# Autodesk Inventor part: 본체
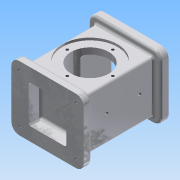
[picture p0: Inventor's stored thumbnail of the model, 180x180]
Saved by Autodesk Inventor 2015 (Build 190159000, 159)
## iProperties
Created: 2017-08
Part Number: 본체
Material: 알루미늄 6061
Document SubType Name: Modeling
Designer: Administrator
Density: 2.7 g/cm^3
Appearance: 알루미늄 - 평지
Author: Administrator
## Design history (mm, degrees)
sketch "스케치1"
  geometry: L1 (46, 41)-(-46, 41); L2 (-46, 41)-(-46, -41); L3 (-46, -41)-(46, -41); L4 (46, -41)-(46, 41); L5 (46, 41)-(-46, -41); L6 (-46, 41)-(46, -41); 1 further point
  constraints: 12 end point, 2 midpoint, 2 parallel, 1 horizontal, 1 perpendicular
  dimensions: "d0" = 92 distance of L2.end L3.end; "d1" = 82 distance of L1.end L2.end
extrude "돌출1" new body sketch "스케치1" distance "d2" = 10; taper "d3" = 0 deg
sketch "스케치2"
  geometry: L1 (-37, -33)-(37, -33); L2 (37, -33)-(37, 33); L3 (37, 33)-(-37, 33); L4 (-37, 33)-(-37, -33); L5 (-37, -33)-(37, 33); L6 (37, -33)-(-37, 33); 1 further point
  constraints: 12 end point, 2 midpoint, 2 parallel, 1 horizontal, 1 perpendicular
  dimensions: "d4" = 74 distance of L2.end L3.end; "d5" = 66 distance of L1.end L2.end
extrude "돌출2" join sketch "스케치2" distance "d6" = 88; taper "d7" = 0 deg
sketch "스케치3"
  geometry: L1 (-46, -41)-(46, -41); L2 (46, -41)-(46, 41); L3 (46, 41)-(-46, 41); L4 (-46, 41)-(-46, -41); L5 (-46, -41)-(46, 41); L6 (46, -41)-(-46, 41); 1 further point
  constraints: 12 end point, 2 midpoint, 2 parallel, 1 horizontal, 1 perpendicular
  dimensions: "d8" = 92 distance of L2.end L3.end; "d9" = 82 distance of L1.end L2.end
extrude "돌출3" join sketch "스케치3" distance "d10" = 10; taper "d11" = 0 deg
sketch "스케치4"
  geometry: L1 (-24, -24)-(24, -24); L2 (24, -24)-(24, 24); L3 (24, 24)-(-24, 24); L4 (-24, 24)-(-24, -24); L5 (-24, -24)-(24, 24); L6 (24, -24)-(-24, 24); 1 further point
  constraints: 12 end point, 2 midpoint, 2 parallel, 1 horizontal, 1 perpendicular
  dimensions: "d12" = 48 distance of L2.end L3.end; "d13" = 48 distance of L1.end L2.end
extrude "돌출4" cut sketch "스케치4" distance "d14" = 16; taper "d15" = 0 deg
sketch "스케치5"
  geometry: L1 (-26, -26)-(26, -26); L2 (26, -26)-(26, 26); L3 (26, 26)-(-26, 26); L4 (-26, 26)-(-26, -26); L5 (-26, -26)-(26, 26); L6 (26, -26)-(-26, 26); 1 further point
  constraints: 12 end point, 2 midpoint, 2 parallel, 1 horizontal, 1 perpendicular
  dimensions: "d16" = 52 distance of L2.end L3.end; "d17" = 52 distance of L1.end L2.end
extrude "돌출5" cut sketch "스케치5" distance "d18" = 8; taper "d19" = 0 deg
sketch "스케치10"
  geometry: L1 (-9, -10)-(83, -10) reference; C1 r 35 at (37, 44); 2 further points
  constraints: 1 centre point, 1 midpoint, 1 vertical alignment
  dimensions: "d26" = 54 distance from line of L1 C1.centre; "d27" = 70 diameter of C1
extrude "돌출7" cut sketch "스케치10" distance "d28" = 3; taper "d29" = 0 deg
sketch "스케치11"
  geometry: C1 r 24 at (0, 0); C2 r 35 at (0, 0) reference; 1 further point
  constraints: 1 centre point, 1 concentric
  dimensions: "d30" = 48 diameter of C1
extrude "돌출8" cut sketch "스케치11" distance "d31" = 8; taper "d32" = 0 deg
sketch "스케치12"
  geometry: C1 r 35 at (37, 44); C2 r 24 at (37, 44) reference; 1 further point
  constraints: 1 centre point, 1 concentric
  dimensions: "d33" = 70 diameter of C1
extrude "돌출9" cut sketch "스케치12" distance "d34" = 3; taper "d35" = 0 deg
sketch "스케치13"
  geometry: C1 r 24 at (0, 0); C2 r 24 at (0, 0) reference; 1 further point
  constraints: 1 centre point, 1 concentric
  dimensions: "d36" = 48 diameter of C1
extrude "돌출10" cut sketch "스케치13" distance "d37" = 8; taper "d38" = 0 deg
sketch "스케치14"
  geometry: L1 (-22, -22)-(22, -22); L2 (22, -22)-(22, 22); L3 (22, 22)-(-22, 22); L4 (-22, 22)-(-22, -22); L5 (-22, -22)-(22, 22); L6 (22, -22)-(-22, 22); 1 further point
  constraints: 12 end point, 2 midpoint, 2 parallel, 1 horizontal, 1 perpendicular
  dimensions: "d39" = 44 distance of L2.end L3.end; "d40" = 44 distance of L1.end L2.end
extrude "돌출11" cut sketch "스케치14" distance "d41" = 74; taper "d42" = 0 deg
sketch "스케치15"
  geometry: L1 (-46, -54)-(46, -54) reference; C1 r 24 at (0, 0); C2 r 24 at (0, 0) reference; 2 further points
  constraints: 1 centre point, 1 concentric, 1 midpoint, 1 vertical alignment
  dimensions: "d43" = 48 diameter of C1
extrude "돌출12" cut sketch "스케치15" stored distance "d44" = 74; taper "d45" = 0 deg
sketch "스케치16"
  geometry: L1 (-46, -54)-(46, -54) reference; 3 further points
  constraints: 1 midpoint, 1 vertical alignment
  dimensions: "d46" = 83 distance from line of point (0, 29) L1
node "작업 평면1"
sketch "스케치17"
  geometry: L1 (-46, -41)-(-46, 41) reference; L2 (-46, 41)-(46, 41) reference; 2 further points
  dimensions: "d57" = 10 distance from line of L1 point (-36, 31); "d58" = 10 distance from line of L2 point (-36, 31)
node "작업 평면2"
sketch "스케치18"
  geometry: L1 (-8, -10)-(74, -10) reference; 3 further points
  constraints: 1 midpoint, 1 vertical alignment
  dimensions: "d72" = 38 distance from line of L1 point (33, 28)
hole "구멍3" sketch "스케치18" at (33, 28) diameter "d73" = 4.459; stored, may be unused: countersink angle "d77" = 90 deg, drill point angle "d79" = 118 deg; dims "d74" = 10, "d75" = 4, "d76" = 2, "d78" = 12.8
fillet "모깎기3" dims "d85" = 3
hole "구멍4" sketch "스케치17" diameter "d86" = 3.459; stored, may be unused: countersink angle "d90" = 90 deg, drill point angle "d92" = 118 deg; dims "d87" = 4, "d88" = 4, "d89" = 2, "d91" = 6
fillet "모깎기4" dims "d99" = 10
fillet "모깎기5" dims "d100" = 10
fillet "모깎기6" dims "d101" = 3
fillet "모깎기7" dims "d102" = 3
fillet "모깎기8" dims "d103" = 3
fillet "모깎기9" dims "d104" = 3
fillet "모깎기10" dims "d105" = 3
fillet "모깎기11" dims "d106" = 3
chamfer "모따기1" distance "d109" = 1; stored, may be unused: second distance "d110" = 2, angle "d111" = 45 deg
hole "구멍5" sketch "스케치16" diameter "d118" = 3.459; stored, may be unused: countersink angle "d122" = 90 deg, drill point angle "d124" = 118 deg; dims "d119" = 4, "d120" = 4, "d121" = 2, "d123" = 6
node "솔리드1"
pattern_linear "직사각형 패턴2" dims "d82" = 42
pattern_linear "직사각형 패턴4" dims "d114" = 72, "d117" = 62
mirror "대칭4"
pattern_circular "원형 패턴2" dims angle "d126" = 360 deg
mirror "대칭5"
